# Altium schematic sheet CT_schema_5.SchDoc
size 287 x 169 mm
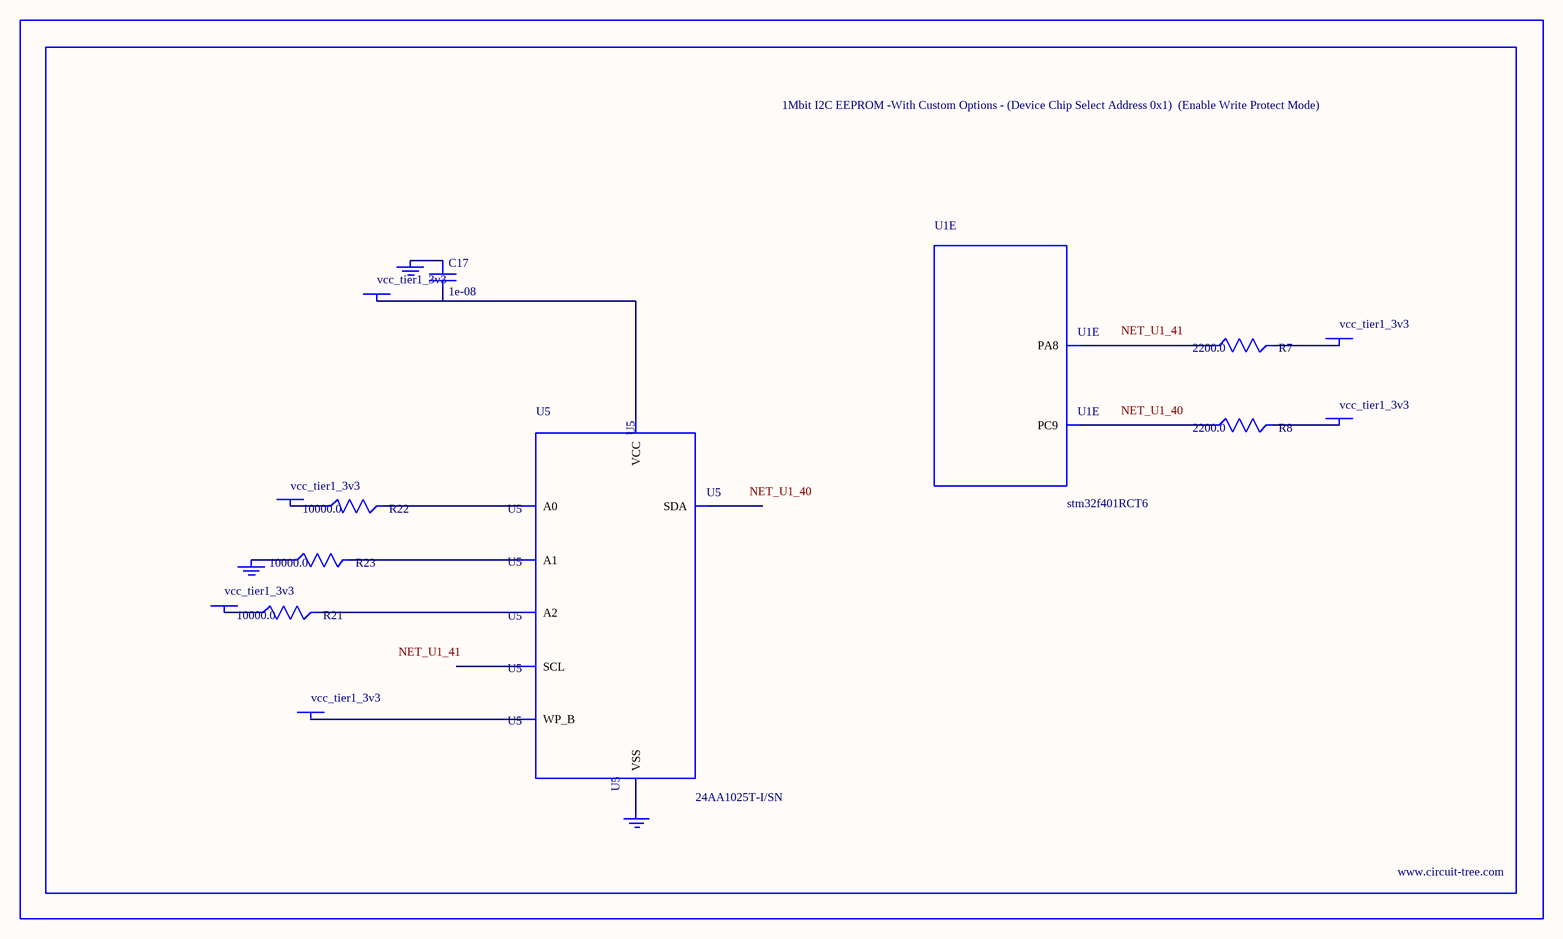
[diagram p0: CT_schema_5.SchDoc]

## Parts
BORDER4  (no value)
C17  1e-08  [C0402]
GND_INSTANCE_4_0  (no value)
GND_INSTANCE_4_1  (no value)
GND_INSTANCE_4_2  (no value)
POWER_INSTANCE_4_0  vcc_tier1_3v3
POWER_INSTANCE_4_1  vcc_tier1_3v3
POWER_INSTANCE_4_2  vcc_tier1_3v3
POWER_INSTANCE_4_3  vcc_tier1_3v3
POWER_INSTANCE_4_4  vcc_tier1_3v3
POWER_INSTANCE_4_5  vcc_tier1_3v3
R7  2200.0  [R0603]
R8  2200.0  [R0603]
R21  10000.0  [R0603]
R22  10000.0  [R0603]
R23  10000.0  [R0603]
U1  stm32f401RCT6  [LQFP64]  (part E of 9)
U5  24AA1025T-I/SN  [SOIC-8]

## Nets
NetC17_1: C17.1 GND_INSTANCE_4_1.0(GND)
NetC17_2: C17.2 POWER_INSTANCE_4_3.0(PWR) U5.8(VCC)
NetGND_INSTANCE_4_0_0: GND_INSTANCE_4_0.0(GND) R23.1
NetGND_INSTANCE_4_2_0: GND_INSTANCE_4_2.0(GND) U5.4(VSS)
NetPOWER_INSTANCE_4_0_0: POWER_INSTANCE_4_0.0(PWR) R22.1
NetPOWER_INSTANCE_4_1_0: POWER_INSTANCE_4_1.0(PWR) R21.1
NetPOWER_INSTANCE_4_2_0: POWER_INSTANCE_4_2.0(PWR) U5.7(WP_B)
NetPOWER_INSTANCE_4_4_0: POWER_INSTANCE_4_4.0(PWR) R8.2
NetPOWER_INSTANCE_4_5_0: POWER_INSTANCE_4_5.0(PWR) R7.2
NetR7_1: R7.1 U1.41(PA8)
NetR8_1: R8.1 U1.40(PC9)
NetR21_2: R21.2 U5.3(A2)
NetR22_2: R22.2 U5.1(A0)
NetR23_2: R23.2 U5.2(A1)

Not connected (* = marked no-connect by the designer): U5 5(SDA) 6(SCL)

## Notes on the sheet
- Labels drawn without touching a wire or pin: NET_U1_40, NET_U1_41

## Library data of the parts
BORDER4 = BORDER_PAGE4
C17 = C0402C103K3RAC
GND_INSTANCE_4_0-GND_INSTANCE_4_2 = GND
POWER_INSTANCE_4_0-POWER_INSTANCE_4_5 = PWR
R7 R8 = RC0603JR-072K2L
R21-R23 = RC0603JR-0710KL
